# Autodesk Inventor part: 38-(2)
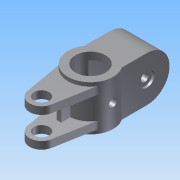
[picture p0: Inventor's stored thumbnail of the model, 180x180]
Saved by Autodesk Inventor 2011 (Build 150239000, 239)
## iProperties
Created: 2014-02
Part Number: 38-(2)
Document SubType Name: Modeling
Designer: Administrator
Density: 1 g/cm^3
Author: Administrator
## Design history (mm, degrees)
sketch "草图1"
  geometry: C1 r 30 at (0, 0); 1 further point
  constraints: 1 centre point, 1 coincident
  dimensions: "d0" = 60 diameter of C1
extrude "拉伸1" new body sketch "草图1" stored distance "d1" = 60; taper "d2" = 0 deg
hole "Hole1" diameter "d5" = 40; stored, may be unused: countersink angle "d9" = 90 deg, drill point angle "d11" = 118 deg; dims "d3" = 10, "d4" = 10, "d6" = 6, "d7" = 4, "d8" = 2, "d10" = 8
node "工作平面1"
sketch "草图2"
  geometry: L1 (-25, -16.583)-(-15.745, -67.843); L2 (25, -16.583)-(15.745, -67.843); A1 r 30 centre (0, 0) between (-25, -16.583) and (25, -16.583) reference; A2 r 16 centre (0, -65) between (-15.745, -67.843) and (15.745, -67.843); 1 further point
  constraints: 4 end point, 4 point on circle, 2 tangent, 1 centre point, 1 vertical alignment
  dimensions: "d13" = 32 diameter of A2; "d14" = 65 distance of A2.centre point (0, 0)
extrude "拉伸2" join sketch "草图2" distance "d16" = 10; taper "d17" = 0 deg
hole "Hole2" diameter "d20" = 20; stored, may be unused: countersink angle "d24" = 90 deg, drill point angle "d26" = 118 deg; dims "d18" = 10, "d19" = 10, "d21" = 6, "d22" = 4, "d23" = 2, "d25" = 8
mirror "镜像1"
sketch "草图3"
  geometry: L1 (-67.843, -15)-(-16.583, -15) reference; L2 (-67.843, 15)-(-16.583, 15) reference; L3 (-42, -15)-(-42, 15); 1 further point
  constraints: 2 end point, 2 point on line, 1 perpendicular
  dimensions: "d27" = 42 distance from line of point (0, 0) L3
feature "加强筋1" sketch "草图3" dims "d28" = 1, "d29" = 6, "d30" = 0
node "工作平面2"
sketch "草图4"
  geometry: L1 (-30, 30)-(30, 30) reference; L2 (30, -30)-(-30, -30) reference; C1 r 12.5 at (0, 0); 1 further point
  constraints: 1 centre point, 1 coincident
  dimensions: "d32" = 25 diameter of C1
extrude "拉伸3" join sketch "草图4" stored distance "d33" = 10; taper "d34" = 0 deg
hole "Hole3" diameter "d37" = 10; stored, may be unused: countersink angle "d41" = 90 deg, drill point angle "d43" = 118 deg; dims "d35" = 10, "d36" = 10, "d38" = 6, "d39" = 20, "d40" = 4, "d42" = 8
node "工作平面3"
sketch "草图5"
  geometry: 2 further points
  constraints: 1 coincident
hole "Hole4" sketch "草图5" at (0, 0) diameter "d45" = 15; stored, may be unused: countersink angle "d49" = 90 deg, drill point angle "d51" = 0 deg; dims "d46" = 6, "d47" = 20, "d48" = 4, "d50" = 20
sketch "草图6"
  geometry: L1 (25, 16.583)-(25, 50); L2 (-25, 50)-(-25, 16.583); L3 (-25, 50)-(25, 50); A1 r 30 centre (0, 0) between (-25, 16.583) and (25, 16.583) reference; 2 further points
  constraints: 6 end point, 2 point on circle, 1 coincident, 1 parallel, 1 perpendicular
extrude "拉伸4" join sketch "草图6" stored distance "d56" = 60; taper "d57" = 0 deg
node "工作平面4"
sketch "草图9"
  geometry: L1 (-15.612, 12.5)-(15.612, 12.5); L2 (15.612, 12.5)-(15.612, 50); L3 (-15.612, 50)-(-15.612, 12.5); L4 (8, 12.5)-(15.612, 12.5) reference; L5 (-15.612, 50)-(15.612, 50); 3 further points
  constraints: 8 end point, 2 parallel, 1 horizontal, 1 midpoint, 1 perpendicular, 1 vertical alignment, 1 other
sketch "草图10"
  geometry: L1 (50, -30)-(50, 30) reference; L2 (50, -30)-(50, 30) reference; L3 (50, -30)-(50, 30); A1 r 30 centre (50, 0) between (50, -30) and (50, 30); 3 further points
  constraints: 4 end point, 2 point on circle, 1 centre point, 1 collinear
extrude "拉伸5" join sketch "草图10" stored distance "d76" = 50; taper "d77" = 0 deg
extrude "拉伸6" cut sketch "草图9" stored distance "d78" = 40; taper "d79" = 0 deg
sketch "草图11"
  geometry: 2 further points
  constraints: 1 coincident
hole "Hole7" sketch "草图11" at (0, 0) diameter "d80" = 10; stored, may be unused: countersink angle "d84" = 90 deg, drill point angle "d86" = 118 deg; dims "d81" = 6, "d82" = 20, "d83" = 3, "d85" = 40
sketch "草图12"
  geometry: 2 further points
  dimensions: "d87" = 50 distance of point (30, 33.417) point (30, -16.583)
hole "Hole8" sketch "草图12" at (30, 33.417) diameter "d88" = 10; stored, may be unused: countersink angle "d92" = 90 deg, drill point angle "d94" = 118 deg; dims "d89" = 6, "d90" = 20, "d91" = 3, "d93" = 40
sketch "草图13"
  geometry: L1 (50, -20)-(50, 20); A1 r 20 centre (50, 0) between (50, -20) and (50, 20); 1 further point
  constraints: 2 end point, 2 point on circle, 1 centre point, 1 vertical
extrude "拉伸7" cut sketch "草图13" stored distance "d95" = 32; taper "d96" = 0 deg
sketch "草图14"
  geometry: L1 (15.612, 50)-(-15.612, 50) reference; L2 (-5, 27)-(5, 27); L3 (5, 27)-(5, 45); L4 (5, 45)-(-5, 45); L5 (-5, 45)-(-5, 27); A1 r 20 centre (0, 0) between (15.612, 12.5) and (-15.612, 12.5) reference; 1 further point
  constraints: 8 end point, 2 parallel, 1 horizontal, 1 midpoint, 1 perpendicular, 1 vertical alignment
  dimensions: "d97" = 18 distance of L2.end L3.end; "d98" = 10 distance of L2.start L2.end; "d99" = 5 distance between parallel lines of L1 L4
extrude "拉伸8" cut sketch "草图14" stored distance "d100" = 40; taper "d101" = 0 deg
fillet "圆角1" dims "d102" = 13
fillet "圆角2" dims "d103" = 13
fillet "圆角3" dims "d104" = 13
fillet "圆角4" dims "d105" = 13
node "实体1"
other parameters: "d12" = 25, "d31" = 8
